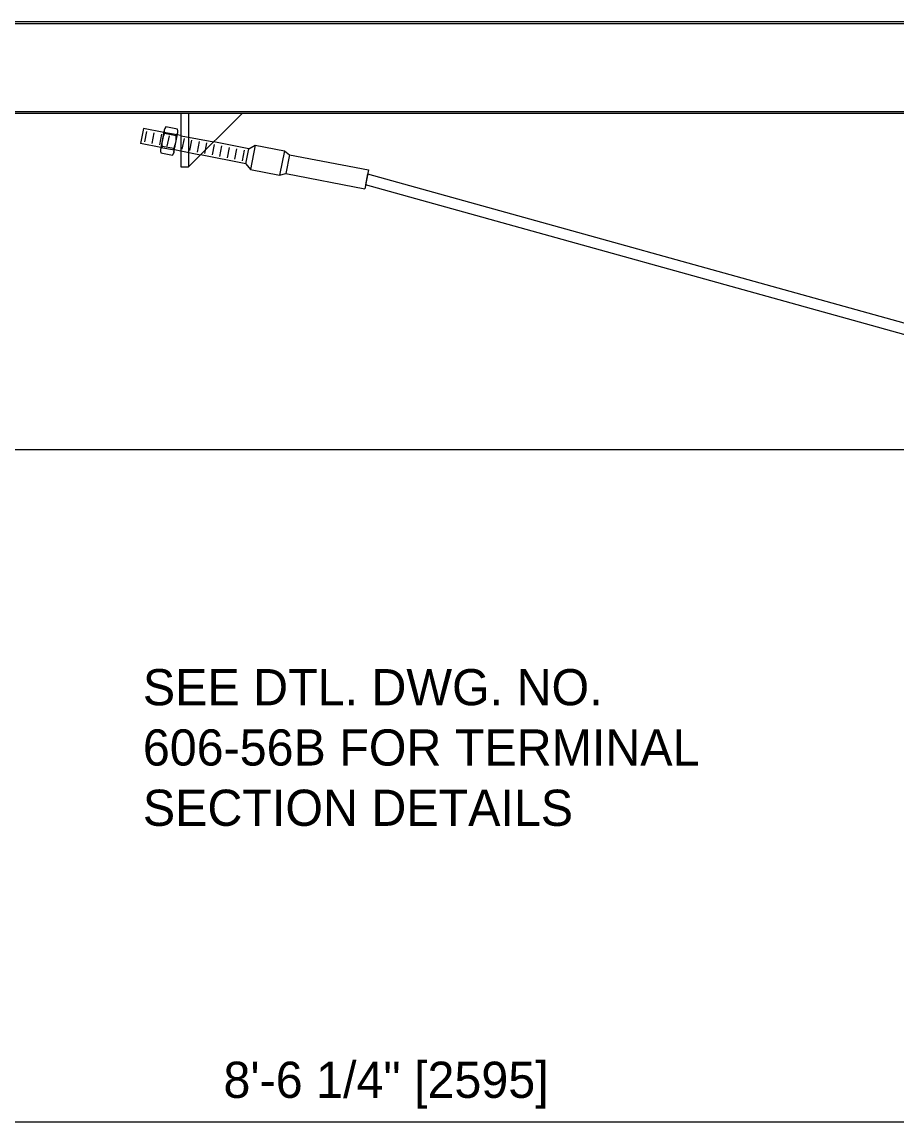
# Model space of a CAD drawing. Extents: x 49991.4 to 50021, y 49987.6 to 50011.4.
# Drawn here: x 50013.742 to 50015.193, y 49993.31 to 49995.135 of the extents above; entities that cross this region are included whole.
import ezdxf

# ---------------------------------------------------------------- set-up
doc = ezdxf.new("R2010")
doc.units = 0
for name, color, linetype in [('Level 1', 7, 'Continuous'), ('Level 2', 7, 'Continuous'), ('Level 3', 7, 'Continuous'), ('Level 4', 7, 'Continuous')]:
    doc.layers.add(name, color=color, linetype=linetype)

msp = doc.modelspace()

# ---------------------------------------------------------------- linework, layer by layer
at = {"layer": 'Level 1'}
for p, q in [((50015.8847, 49995.1348), (50012.2287, 49995.1348)), ((50015.4023, 49994.9829), (50012.2287, 49994.9829)), ((50014.0059, 49994.9829), (50014.0059, 49994.8943)), ((50014.0186, 49994.8943), (50014.1074, 49994.9829)), ((50014.0186, 49994.9829), (50014.0186, 49994.8943)), ((50014.0947, 49994.9829), (50014.082, 49994.9829)), ((50014.1582, 49994.9829), (50014.0947, 49994.9829)), ((50013.9438, 49994.9582), (50013.939, 49994.9334)), ((50013.9775, 49994.9517), (50013.9438, 49994.9582)), ((50013.9783, 49994.9556), (50013.972, 49994.9233)), ((50014.0002, 49994.9569), (50013.9808, 49994.9607)), ((50013.9459, 49994.9359), (50013.9493, 49994.9533)), ((50013.9584, 49994.9335), (50013.9617, 49994.9509)), ((50013.9708, 49994.9311), (50013.9742, 49994.9485)), ((50013.9981, 49994.9462), (50013.9787, 49994.9499)), ((50013.9943, 49994.919), (50014.0006, 49994.9513)), ((50013.9958, 49994.9263), (50013.9991, 49994.9437)), ((50014.0059, 49994.9463), (50013.9999, 49994.9474)), ((50014.1183, 49994.9245), (50014.0602, 49994.9358)), ((50013.9727, 49994.9269), (50013.939, 49994.9334)), ((50013.9725, 49994.9176), (50013.9918, 49994.9139)), ((50013.9939, 49994.9247), (50013.9745, 49994.9284)), ((50014.0059, 49994.9205), (50013.995, 49994.9226)), ((50014.0456, 49994.9167), (50014.0467, 49994.9224)), ((50014.0581, 49994.9142), (50014.0614, 49994.9316)), ((50014.0705, 49994.9118), (50014.0739, 49994.9292)), ((50014.083, 49994.9094), (50014.0864, 49994.9268)), ((50014.0955, 49994.907), (50014.0988, 49994.9244)), ((50014.1079, 49994.9046), (50014.1113, 49994.922)), ((50014.1134, 49994.8997), (50014.1183, 49994.9245)), ((50014.1183, 49994.9245), (50014.1291, 49994.9305)), ((50014.1291, 49994.9305), (50014.1213, 49994.8901)), ((50014.1291, 49994.9305), (50014.1774, 49994.9212)), ((50014.1774, 49994.9212), (50014.1696, 49994.8808)), ((50014.1774, 49994.9212), (50014.1858, 49994.9147)), ((50014.1134, 49994.8997), (50014.0385, 49994.9142)), ((50014.1134, 49994.8997), (50014.1213, 49994.8901)), ((50014.1858, 49994.9147), (50014.1798, 49994.8836)), ((50014.1858, 49994.9147), (50014.3167, 49994.8894)), ((50014.0059, 49994.8943), (50014.0186, 49994.8943)), ((50014.1213, 49994.8901), (50014.1696, 49994.8808)), ((50014.1696, 49994.8808), (50014.1798, 49994.8836)), ((50014.1798, 49994.8836), (50014.3107, 49994.8583)), ((50014.3167, 49994.8894), (50014.3107, 49994.8583)), ((50014.3155, 49994.8832), (50014.3119, 49994.8646)), ((50014.3155, 49994.8832), (50015.5107, 49994.5507)), ((50015.5077, 49994.5319), (50014.3119, 49994.8646)), ((49999.8098, 49994.4259), (50016.5942, 49994.4259))]:
    msp.add_line(p, q, dxfattribs=at)
for centre, major_axis, start_param, end_param in [((50013.9888, 49994.9536), (-0.0107, 0), 5.551058, 6.632461), ((50013.9901, 49994.9533), (-0.0107, 0), 2.409466, 3.490868), ((50014.0148, 49994.9318), (-0.0404, 0), 5.816377, 6.367141), ((50013.9578, 49994.9428), (-0.0404, 0), 2.674785, 3.22555), ((50013.9825, 49994.9213), (-0.0107, 0), 5.551058, 6.632461), ((50013.9839, 49994.921), (-0.0107, 0), 2.409466, 3.490868)]:
    msp.add_ellipse(centre, major_axis=major_axis, ratio=0.997137, start_param=start_param, end_param=end_param, dxfattribs=at)
at = {"layer": 'Level 3'}
msp.add_line((50013.1586, 49993.3103), (50015.7531, 49993.3103), dxfattribs=at)
at = {"layer": 'Level 4'}
for p, q in [((50015.8847, 49995.1316), (50012.2287, 49995.1316)), ((50015.8847, 49994.986), (50012.2287, 49994.986)), ((50013.9999, 49994.9474), (50013.9775, 49994.9517)), ((50013.9833, 49994.9287), (50013.9867, 49994.9461)), ((50014.0061, 49994.9462), (50014.0602, 49994.9358)), ((50014.0082, 49994.9239), (50014.0116, 49994.9413)), ((50014.0207, 49994.9215), (50014.0241, 49994.9389)), ((50014.0331, 49994.9191), (50014.0365, 49994.9365)), ((50013.9727, 49994.9269), (50013.995, 49994.9226)), ((50014.0386, 49994.9141), (50014.0059, 49994.9205)), ((50014.0467, 49994.9224), (50014.049, 49994.9341))]:
    msp.add_line(p, q, dxfattribs=at)

# ---------------------------------------------------------------- texts
at = {"layer": 'Level 2'}
for s, height, p in [('SEE DTL. DWG. NO.', 0.06, (50013.9428, 49994.0015)), ('606-56B FOR TERMINAL', 0.06, (50013.9428, 49993.9015)), ('SECTION DETAILS', 0.06, (50013.9428, 49993.8015)), ('8\'-6 1/4" [2595]', 0.060033, (50014.0764, 49993.3503))]:
    msp.add_text(s, height=height, dxfattribs=at).set_placement(p)

doc.saveas('drawing.dxf')
